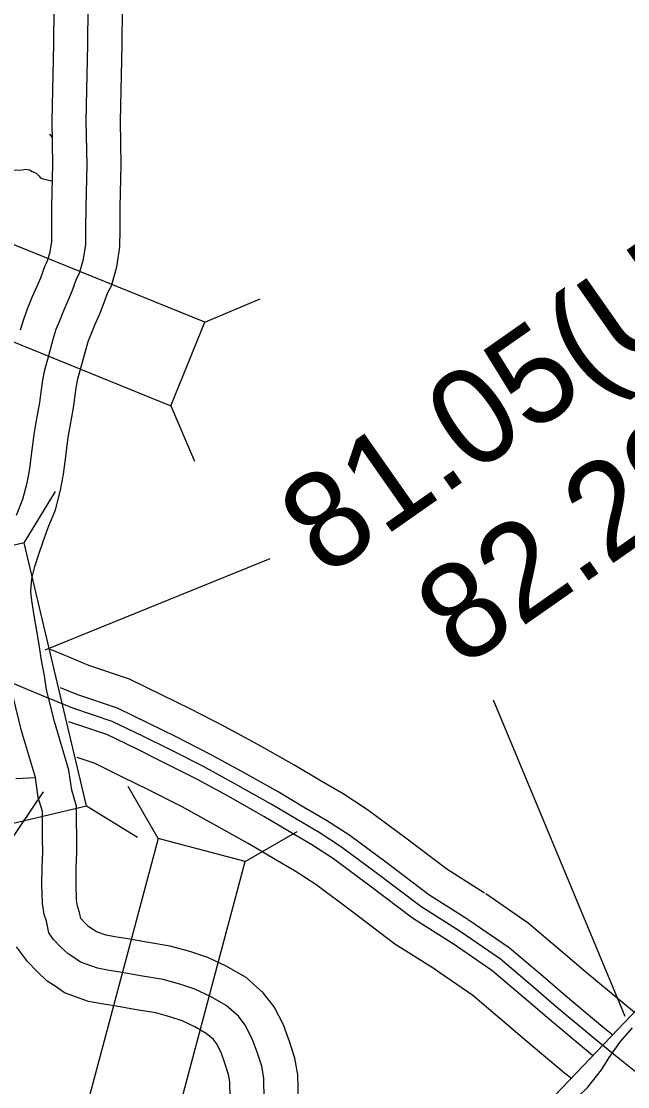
# Model space of a CAD drawing. Extents: x -83719 to 153526, y -11835 to 11446.
# Drawn here: x -1986.7 to -1897.8, y 1296.2 to 1452.3 of the extents above; entities that cross this region are included whole.
import ezdxf

# ---------------------------------------------------------------- set-up
doc = ezdxf.new("R2010")
doc.units = 0
for name, color, linetype in [('Level 10', 7, 'Continuous'), ('Level 19', 7, 'Continuous'), ('Level 20', 7, 'Continuous'), ('Level 58', 7, 'Continuous'), ('Level 59', 7, 'Continuous'), ('Level 9', 7, 'Continuous')]:
    doc.layers.add(name, color=color, linetype=linetype)

msp = doc.modelspace()

# ---------------------------------------------------------------- linework, layer by layer
at = {"layer": 'Level 10'}
for points in [[(-1986.83, 1407.14), (-1986.31, 1408.86), (-1985.78, 1410.22), (-1985.1, 1411.91), (-1984.42, 1413.43), (-1983.87, 1414.76), (-1983.2, 1416.57), (-1982.86, 1417.26), (-1982.48, 1418.56), (-1982.25, 1420.06), (-1982.23, 1421.96), (-1982.22, 1425.28), (-1982.08, 1431.34), (-1982.19, 1437.75), (-1981.94, 1449.06), (-1981.89, 1454.39)], [(-1946.1, 1294.25), (-1946.16, 1297.97), (-1946.62, 1300.43), (-1947.38, 1302.89), (-1948.26, 1305.3), (-1949.65, 1307.97), (-1951.24, 1310.02), (-1953.77, 1312.25), (-1956.68, 1313.9), (-1959.38, 1315.16), (-1962, 1316.07), (-1964.88, 1316.84), (-1968.38, 1317.41), (-1971.08, 1317.91), (-1973.02, 1318.21), (-1974.25, 1318.43), (-1975.71, 1318.96), (-1976.26, 1319.34), (-1976.79, 1319.67), (-1977.39, 1320.24), (-1978, 1320.87), (-1978.17, 1321.76), (-1978.48, 1322.7), (-1978.64, 1323.56), (-1978.68, 1325.92), (-1978.65, 1328.27), (-1978.55, 1330.58), (-1978.59, 1332.6), (-1978.6, 1335.47), (-1978.63, 1337.34), (-1979.32, 1339.7), (-1979.74, 1342.61), (-1981.85, 1349.73), (-1983.01, 1354.38), (-1983.29, 1356.45), (-1983.74, 1358.72), (-1984.14, 1361.33), (-1984.4, 1362.73), (-1984.69, 1364.4), (-1984.94, 1365.92), (-1985.15, 1367.48), (-1985.3, 1368.75), (-1985.29, 1369.47), (-1985.15, 1370.7), (-1984.74, 1372.47), (-1984.14, 1374.27), (-1983.57, 1376), (-1982.77, 1378.19), (-1981.7, 1380.76), (-1980.99, 1383.66), (-1980.54, 1385.97), (-1980.25, 1388.18), (-1979.85, 1391.39), (-1979.57, 1392.97), (-1979.06, 1395.7), (-1978.68, 1398.66), (-1978.44, 1399.94), (-1977.86, 1402.05), (-1977.22, 1404.37), (-1976.85, 1405.6), (-1976.49, 1406.52), (-1975.89, 1407.99), (-1975.22, 1409.49), (-1974.55, 1411.12), (-1974.01, 1412.6), (-1973.51, 1413.59), (-1972.69, 1416.39), (-1972.26, 1419.24), (-1972.23, 1421.87), (-1972.22, 1425.16), (-1972.08, 1431.32), (-1972.19, 1437.72), (-1971.94, 1448.91), (-1971.89, 1454.26)], [(-1956.11, 1294.55), (-1956.15, 1296.96), (-1956.35, 1298.03), (-1956.86, 1299.69), (-1957.43, 1301.26), (-1958.11, 1302.56), (-1958.56, 1303.14), (-1959.6, 1304.06), (-1961.27, 1305.01), (-1963.13, 1305.88), (-1964.93, 1306.5), (-1966.99, 1307.05), (-1970.1, 1307.56), (-1972.75, 1308.05), (-1974.68, 1308.35), (-1976.85, 1308.74), (-1980.36, 1310), (-1981.76, 1310.99), (-1982.91, 1311.7), (-1984.4, 1313.11), (-1985.82, 1314.57), (-1987.4, 1316.75)], [(-1921.34, 1283.33), (-1920.64, 1283.42), (-1920.24, 1283.6), (-1919.42, 1283.88), (-1919.05, 1284.04), (-1918.46, 1284.31), (-1917.56, 1284.86), (-1915.08, 1286.74), (-1912.8, 1287.97), (-1911.4, 1289.03), (-1910.41, 1289.83), (-1909.51, 1290.62), (-1908.21, 1291.77), (-1903.65, 1296.18), (-1901.69, 1298.71), (-1900.55, 1300.54), (-1898.9, 1302.86), (-1897.11, 1304.87)]]:
    msp.add_lwpolyline(points, dxfattribs=at)
at = {"layer": 'Level 19'}
for points in [[(-1918.82, 1324.62), (-1924.36, 1328.12), (-1930.34, 1332.64), (-1935.95, 1336.8), (-1939.55, 1339.15), (-1943, 1341.17), (-1946.77, 1343.4), (-1952.15, 1346.44), (-1956.93, 1349.04), (-1961.97, 1351.59), (-1965.98, 1353.58), (-1970.86, 1355.95), (-1976.83, 1357.95), (-1980.55, 1359.5), (-1982.45, 1360.28)], [(-1921.27, 1320.75), (-1926.98, 1324.35), (-1933.08, 1328.98), (-1938.57, 1333.04), (-1941.96, 1335.25), (-1945.33, 1337.22), (-1949.07, 1339.43), (-1954.38, 1342.43), (-1959.06, 1344.99), (-1964.03, 1347.49), (-1968, 1349.47), (-1972.59, 1351.7), (-1978.44, 1353.66), (-1980.96, 1354.71)], [(-1923.49, 1317.22), (-1929.35, 1320.92), (-1935.58, 1325.64), (-1940.95, 1329.61), (-1944.15, 1331.7), (-1947.44, 1333.63), (-1951.16, 1335.83), (-1956.4, 1338.79), (-1960.99, 1341.3), (-1965.89, 1343.77), (-1969.84, 1345.73), (-1974.17, 1347.83), (-1979.74, 1349.7)], [(-1925.94, 1313.35), (-1931.96, 1317.15), (-1938.33, 1321.97), (-1943.56, 1325.85), (-1946.56, 1327.8), (-1949.76, 1329.68), (-1953.45, 1331.86), (-1958.63, 1334.78), (-1963.12, 1337.24), (-1967.95, 1339.67), (-1971.86, 1341.62), (-1975.91, 1343.58), (-1978.54, 1344.46)], [(-1896.84, 1307.1), (-1898.56, 1308.52), (-1903.99, 1313.04), (-1907.27, 1315.85), (-1912.42, 1320.22), (-1918.61, 1324.48)], [(-1900.02, 1303.78), (-1901.48, 1304.99), (-1906.95, 1309.54), (-1910.24, 1312.37), (-1915.21, 1316.58), (-1921.2, 1320.7)], [(-1902.98, 1300.82), (-1904.14, 1301.78), (-1909.64, 1306.36), (-1912.95, 1309.2), (-1917.74, 1313.27), (-1923.56, 1317.27)], [(-1906.09, 1297.45), (-1907.07, 1298.25), (-1912.6, 1302.86), (-1915.92, 1305.71), (-1920.53, 1309.62), (-1926.16, 1313.49)]]:
    msp.add_lwpolyline(points, dxfattribs=at)
at = {"layer": 'Level 20'}
for p, q in [((-1959.82, 1408.24), (-1951.72, 1411.67)), ((-1964.78, 1396.01), (-1961.35, 1387.91)), ((-1986.31, 1375.95), (-1981.69, 1383.44)), ((-1966.64, 1332.62), (-1971.04, 1340.24)), ((-1977.17, 1337.42), (-1969.68, 1332.8)), ((-1953.88, 1329.22), (-1946.26, 1333.62))]:
    msp.add_line(p, q, dxfattribs=at)
for points in [[(-2001.48, 1410.89), (-1964.78, 1396.01), (-1959.82, 1408.24), (-1996.52, 1423.12)], [(-1999.15, 1372.9), (-1990.01, 1334.37), (-1977.17, 1337.42), (-1986.31, 1375.95)], [(-1964.09, 1290.96), (-1953.88, 1329.22), (-1966.64, 1332.62), (-1976.85, 1294.36)], [(-1887.18, 1317.33), (-1914.51, 1288.67), (-1904.96, 1279.56), (-1877.63, 1308.21)]]:
    msp.add_lwpolyline(points, close=True, dxfattribs=at)
at = {"layer": 'Level 58'}
for p, q in [((-1950.28, 1373.6), (-1983.26, 1360.19)), ((-1917.56, 1352.95), (-1898.25, 1306.56)), ((-2000.75, 1313.77), (-1983.46, 1339.47))]:
    msp.add_line(p, q, dxfattribs=at)
at = {"layer": 'Level 59'}
for points in [[(-1987.43, 1380), (-1986.47, 1382.32), (-1985.87, 1384.73), (-1985.47, 1386.78), (-1985.21, 1388.82), (-1984.8, 1392.13), (-1984.49, 1393.87), (-1984, 1396.48), (-1983.62, 1399.45), (-1983.31, 1401.06), (-1982.68, 1403.37), (-1982.02, 1405.75), (-1981.58, 1407.23), (-1981.13, 1408.37), (-1980.49, 1409.95), (-1979.82, 1411.46), (-1979.21, 1412.94), (-1978.61, 1414.59), (-1978.19, 1415.43), (-1977.59, 1417.47), (-1977.26, 1419.65), (-1977.23, 1421.92), (-1977.22, 1425.22), (-1977.08, 1431.33), (-1977.19, 1437.73), (-1976.94, 1448.98), (-1976.89, 1454.33)], [(-1922.38, 1318.98), (-1928.16, 1322.64), (-1934.33, 1327.31), (-1939.76, 1331.32), (-1943.06, 1333.47), (-1946.38, 1335.42), (-1950.11, 1337.63), (-1955.39, 1340.61), (-1960.03, 1343.14), (-1964.96, 1345.63), (-1968.92, 1347.6), (-1973.38, 1349.76), (-1979.17, 1351.71), (-1983.1, 1353.34), (-1987.89, 1355.3)], [(-1951.1, 1294.4), (-1951.15, 1297.47), (-1951.48, 1299.23), (-1952.12, 1301.29), (-1952.85, 1303.28), (-1953.88, 1305.26), (-1954.9, 1306.58), (-1956.69, 1308.16), (-1958.97, 1309.45), (-1961.26, 1310.52), (-1963.46, 1311.28), (-1965.94, 1311.94), (-1969.24, 1312.49), (-1971.91, 1312.98), (-1973.85, 1313.28), (-1975.55, 1313.59), (-1978.03, 1314.48), (-1979.01, 1315.17), (-1979.85, 1315.69), (-1980.9, 1316.67), (-1981.98, 1317.79), (-1982.7, 1318.78), (-1983.02, 1320.51), (-1983.34, 1321.47), (-1983.63, 1323.07), (-1983.68, 1325.9), (-1983.65, 1328.41), (-1983.56, 1330.64), (-1983.59, 1332.54), (-1983.6, 1335.41), (-1983.62, 1336.58), (-1984.22, 1338.64), (-1984.63, 1341.54), (-1986.68, 1348.41), (-1987.92, 1353.43)], [(-1987.49, 1341.42), (-1984.63, 1341.54)], [(-1894.51, 1296.65), (-1899.15, 1300.36), (-1902.81, 1303.38), (-1908.3, 1307.95), (-1911.59, 1310.78), (-1916.47, 1314.92), (-1922.38, 1318.98)]]:
    msp.add_lwpolyline(points, dxfattribs=at)
at = {"layer": 'Level 9'}
for points in [[(-1982.59, 1435.79), (-1982.38, 1435.58), (-1982.17, 1435.32), (-1982.16, 1435.3)], [(-1987.79, 1430.52), (-1986.52, 1430.57), (-1986.09, 1430.68), (-1985.49, 1430.56), (-1985.12, 1430.36), (-1984.75, 1430.2), (-1984.55, 1430.07), (-1984.15, 1429.71), (-1983.88, 1429.42), (-1983.54, 1429.26), (-1982.87, 1429.1), (-1982.47, 1429.01), (-1982.19, 1428.91)]]:
    msp.add_lwpolyline(points, dxfattribs=at)

# ---------------------------------------------------------------- texts
at = {"layer": 'Level 58'}
for s, p in [('81.05(U.P.)', (-1942.16, 1370.72)), ('82.29(U.P.)', (-1922.15, 1357.41))]:
    msp.add_text(s, height=14.08, rotation=35, dxfattribs=at).set_placement(p)

doc.saveas('drawing.dxf')
